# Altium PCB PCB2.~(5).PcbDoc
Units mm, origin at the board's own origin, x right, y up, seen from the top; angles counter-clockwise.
Board outline 101.6 x 109.09 mm, 2 copper layers (Top Layer, Bottom Layer); 25 components, 22 nets, 119 pads, 0 vias.
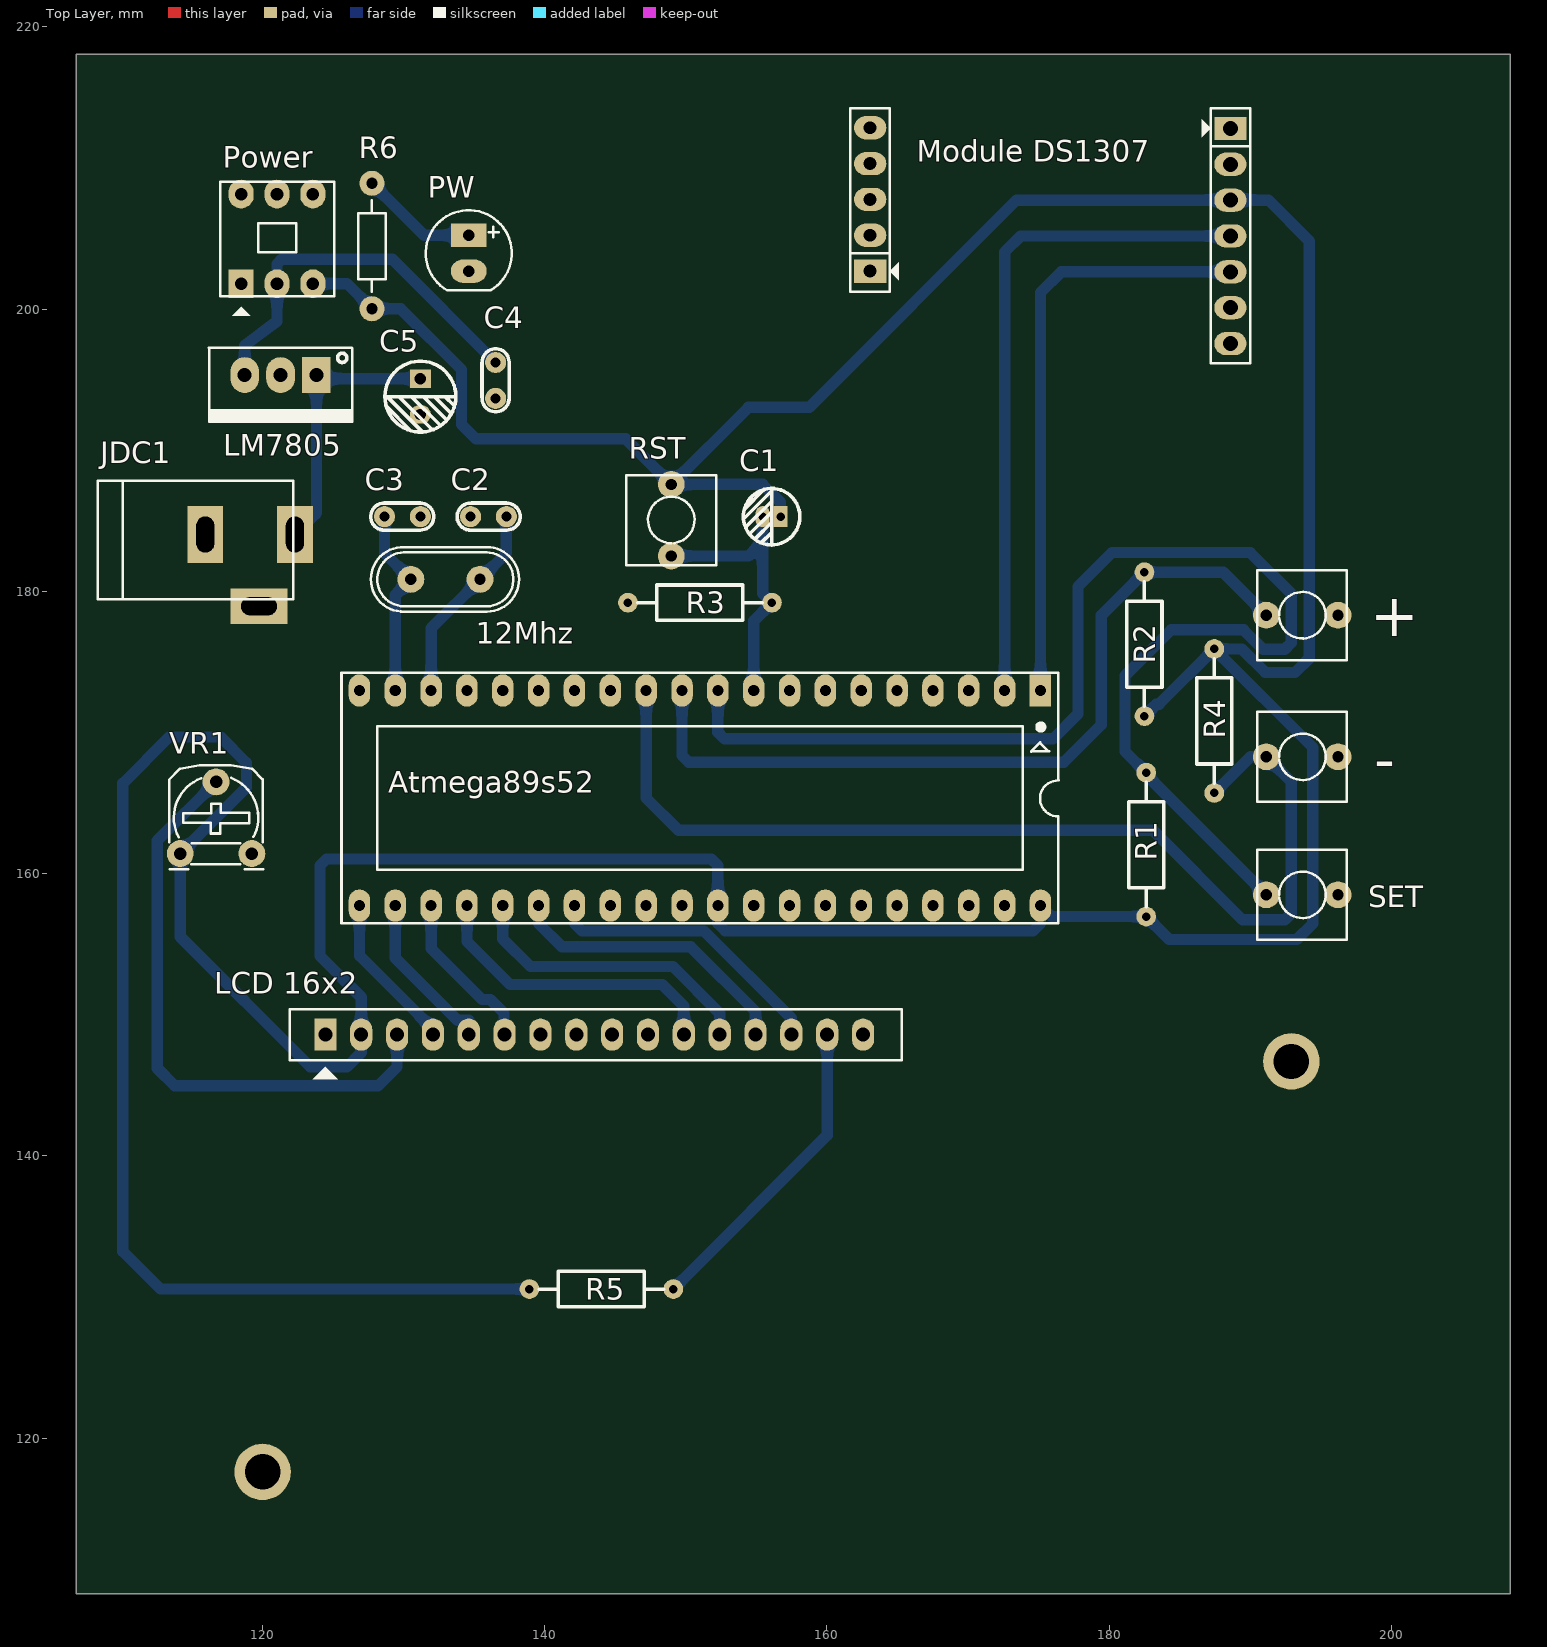
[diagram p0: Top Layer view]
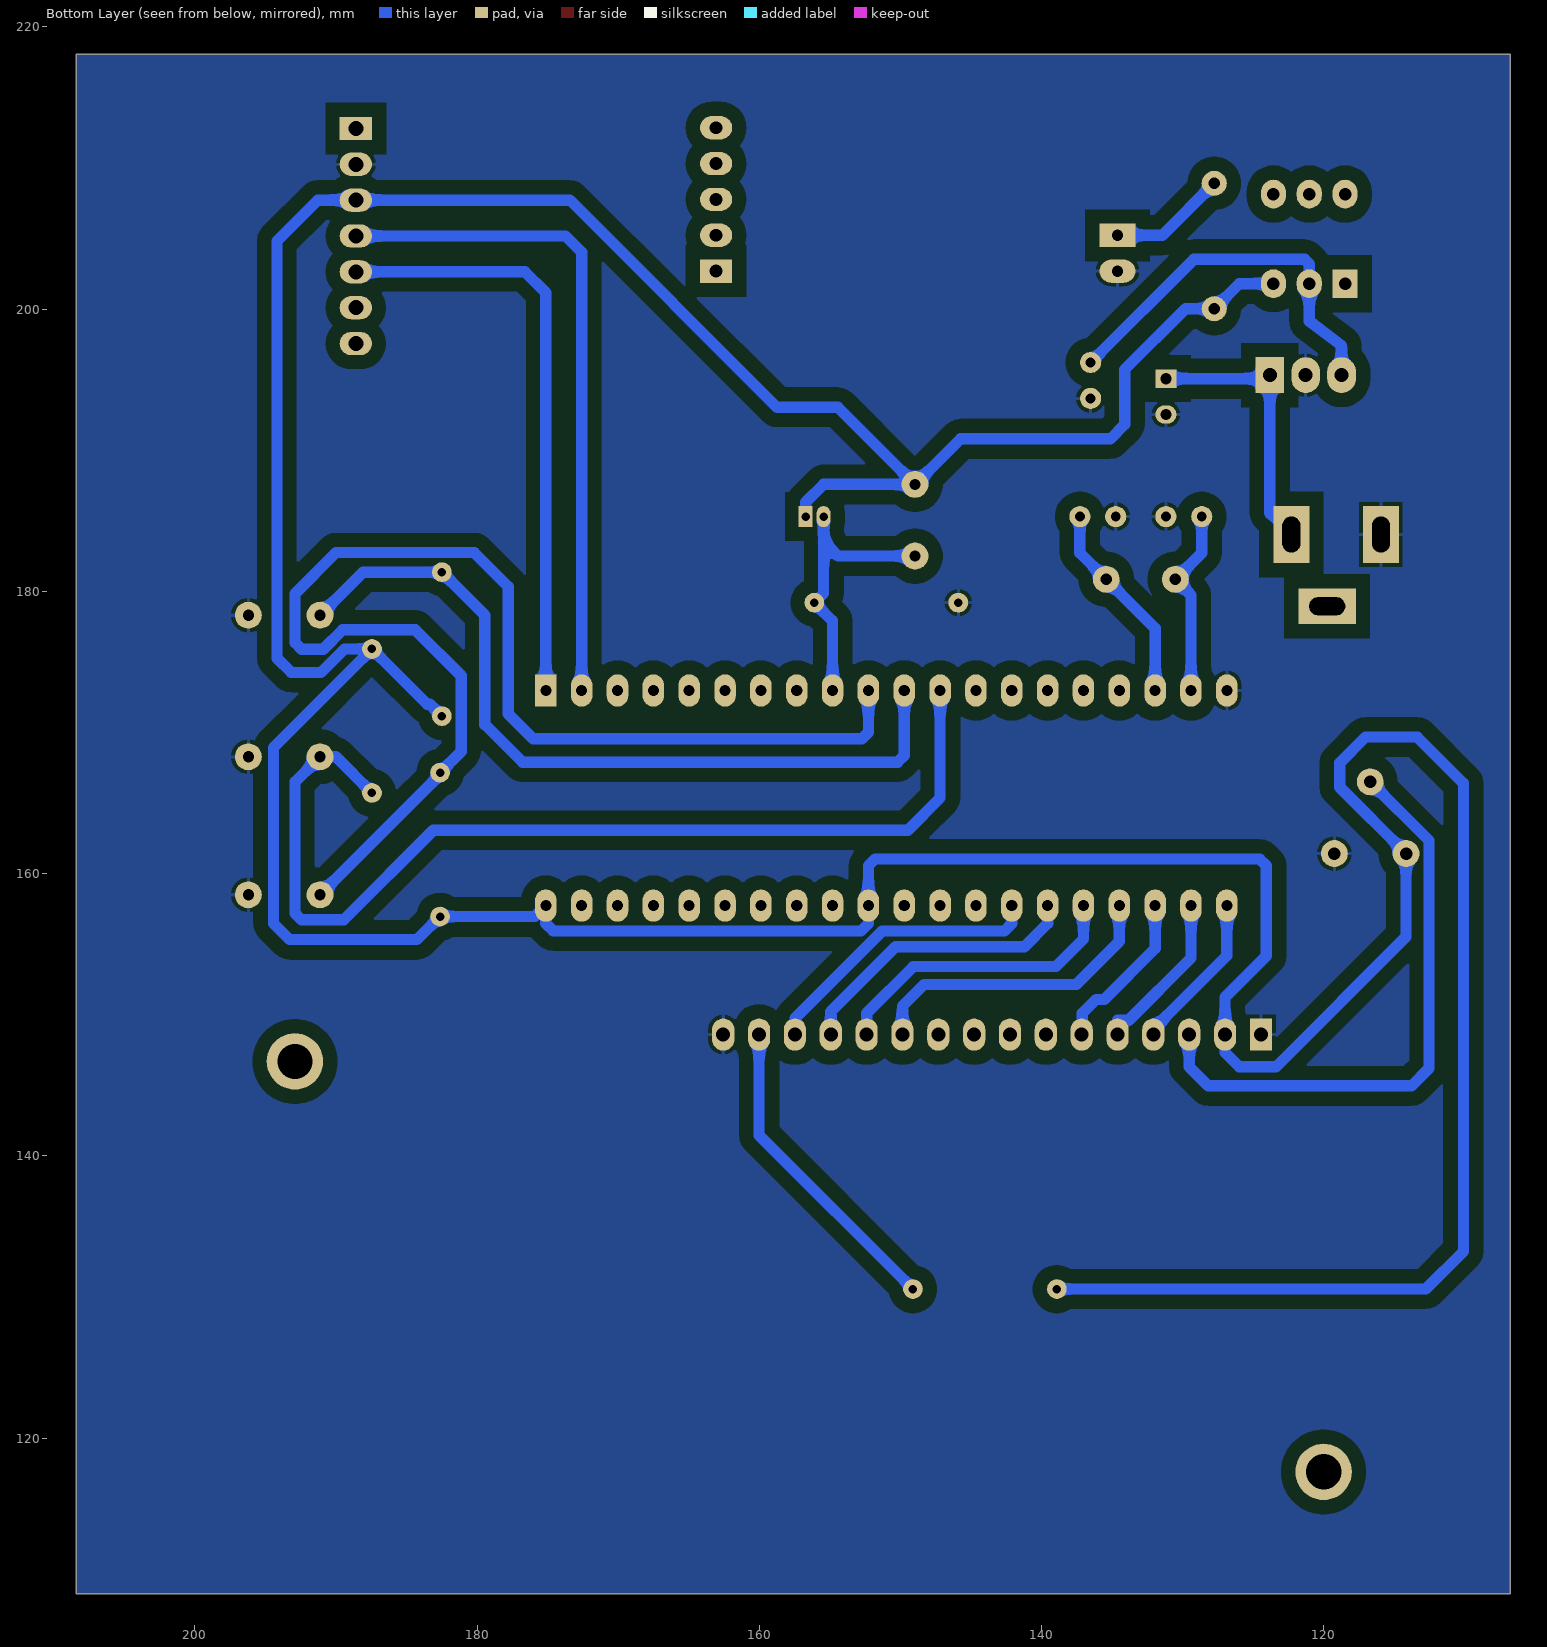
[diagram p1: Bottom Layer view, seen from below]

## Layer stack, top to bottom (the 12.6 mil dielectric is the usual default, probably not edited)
Top Solder: solder mask 0.0102, Solder Resist, Dk 3.5
Top Layer: signal copper 0.0356
Dielectric 1: dielectric 0.32, FR-4, Dk 4.8
Bottom Layer: signal copper 0.0356
Bottom Solder: solder mask 0.0102, Solder Resist, Dk 3.5

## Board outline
106.807,218.059 106.807,108.966 208.407,108.966 208.407,218.059

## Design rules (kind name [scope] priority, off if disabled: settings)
Clearance [All] p1: gap=0.2 ignorepadtopadclearanceinfootprint=FALSE
PolygonConnect [All] p1: connectstyle=Relief reliefconductorwidth=0.254 reliefentries=4 polygonreliefangle="90 Angle" airgapwidth=0.254
RoutingLayers [All] p1: top layer_v5=FALSE bottom layer_v5=TRUE
RoutingVias [All] p1: holewidth=0.711 width=1.27 viastyle="Through Hole" minholewidth=0.711 minwidth=1.27 maxholewidth=0.711 maxwidth=1.27
SolderMaskExpansion [All] p1: expansion=0.102 istentingtop=FALSE
Width [All] p1: maxlimit=0.8 minlimit=0.254 preferedwidth=0.8
29 further rules are at their usual default settings.

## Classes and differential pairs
component class Sheet2: C1 C2 C3 C4 C5 JDC1 R1 R2 R3 R4 R5 R6 VR1

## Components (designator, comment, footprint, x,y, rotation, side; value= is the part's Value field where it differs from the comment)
12Mhz "11Mhz" "Thach Anh 2 chan cam" 132.969,180.848 r0 top value=4Mhz (schematic designator Y1)
+ "SW" SW2 196.215,178.308 r180 top value="SW chip 2 pin" (schematic designator SW3)
- "SW" SW2 196.215,168.275 r180 top value="SW chip 2 pin" (schematic designator SW4)
Atmega89s52 "AT89S52" DIP40/W0.6 175.133,172.974 r180 top (schematic designator IC1)
C1 "10uF" "tu hoa 4mm" 156.083,185.293 r180 top
C2 "30pF" "tu gom" 136.017,185.293 r180 top
C3 "30pF" "tu gom" 129.921,185.293 r0 top
C4 "104" "tu gom" 136.525,194.945 r270 top
C5 "22uF" "tu hoa 5mm" 131.191,193.802 r270 top
JDC1 "Jack DC" DC-IN 119.126,181.483 r0 top value="Jac DC"
JP2 "JP5 PIN" JP5_1 163.068,202.692 r90 top value=JP5
"LCD 16x2" "LCD1602 XL" "LCD1602 with Jump" 124.46,148.59 r0 top (schematic designator LCD1)
LM7805 "LM7805" QTO-220 123.825,195.326 r180 top (schematic designator IC2)
"Module DS1307" "JP7 PIN" JP7_1 188.595,212.801 r270 top value=JP7 (schematic designator JP1)
Power "SW6A" SW6 118.491,201.803 r90 top value=SW6 (schematic designator SW5)
PW "LED" LED-5-RED 134.62,205.232 r270 top value="LED 3 ly Single Colour" (schematic designator LED1)
R1 "10K" "tro vach 1/4w" 182.626,162.052 r90 top
R2 "10K" "tro vach 1/4w" 182.499,176.256 r90 top
R3 "10k" "tro vach 1/4w" 151.003,179.197 r0 top
R4 "10K" "tro vach 1/4w" 187.452,170.815 r270 top
R5 "220R" "tro vach 1/4w" 144.018,130.556 r0 top
R6 "1k" R1/4W 127.762,208.915 r270 top value="R1/4W - 1K"
RST "SW" SW2 148.971,187.579 r270 top value="SW chip 2 pin" (schematic designator SW2)
SET "SW" SW2 196.215,158.496 r180 top value="SW chip 2 pin" (schematic designator SW1)
VR1 "1K" "Bien Tro Tam Giac Dung" 114.173,161.417 r0 top

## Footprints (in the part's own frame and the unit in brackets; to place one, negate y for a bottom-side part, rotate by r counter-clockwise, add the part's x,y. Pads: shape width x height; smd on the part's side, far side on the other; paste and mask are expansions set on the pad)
"Bien Tro Tam Giac Dung" [mil] "RM065"
  round 75 hole 35: 1(0,0) 2(100,200) 3(200,0)
  silkscreen extent -31,-44 231,246, body extent -28,-50 228,228, height 279
DC-IN [mil] "Jac DC input"
  rect 100x160 hole 50 slot 100 at 90 deg: 1(125,100) 2(-125,100)
  rect 160x100 hole 50 slot 100 at 0 deg: 3(25,-100)
  silkscreen extent -425,-80 120,250, body extent -410,-105 134,269, height 434
DIP40/W0.6 [mil] "40 PIN, W 600mil, Pin to pin 100mil"
  rect 60x90 hole 31: 1(0,0)
  oval 60x90 hole 31: 2(100,0) 3(200,0) 4(300,0) 5(400,0) 6(500,0) 7(600,0) 8(700,0) 9(800,0) 10(900,0) 11(1000,0) 12(1100,0) 13(1200,0) 14(1300,0) 15(1400,0) 16(1500,0) 17(1600,0) 18(1700,0) 19(1800,0) 20(1900,0) 21(1900,600) 22(1800,600) 23(1700,600) 24(1600,600) 25(1500,600) 26(1400,600) 27(1300,600) 28(1200,600) 29(1100,600) 30(1000,600) 31(900,600) 32(800,600) 33(700,600) 34(600,600) 35(500,600) 36(400,600) 37(300,600) 38(200,600) 39(100,600) 40(0,600)
  silkscreen extent -50,-50 1950,650, body extent -82,-10 1982,600, height 224
JP5_1 [mil] "JP5"
  rect 65x90 hole 36: 1(0,0)
  oval 65x90 hole 36: 2(100,0) 3(200,0) 4(300,0) 5(400,0)
  silkscreen extent -57,-80 455,55, body extent -55,-48 455,50, height 366
JP7_1 [mil] "JP7"
  rect 65x90 hole 42: 1(0,0)
  oval 65x90 hole 42: 2(100,0) 3(200,0) 4(300,0) 5(400,0) 6(500,0) 7(600,0)
  silkscreen extent -57,-80 655,55, body extent -53,-47 657,51, height 366
"LCD1602 with Jump" [mil] "LCD dipslay 16x2, 16 pin"
  rect 62x90 hole 39: 1(0,0)
  oval 62x90 hole 39: 2(100,0) 3(200,0) 4(300,0) 5(400,0) 6(500,0) 7(600,0) 8(700,0) 9(800,0) 10(900,0) 11(1000,0) 12(1100,0) 13(1200,0) 14(1300,0) 15(1400,0) 16(1500,0)
  silkscreen extent -100,-125 1608,70, body extent -320,-1353 2850,84, height 764
LED-5-RED [mil] "LED 2 PIN, 5 ly , Only colour,pin to pin 100mil"
  rect 65x100 hole 32: 1(0,0)
  oval 65x100 hole 32: 2(100,0)
  silkscreen extent -70,-120 154,120, body extent -65,-119 149,118, height 339
QTO-220 [mil] "TO-220 - 1-2-3"
  rect 80x100 hole 39: 1(0,0)
  oval 80x100 hole 39: 2(100,0) 3(200,0)
  silkscreen extent -100,-76 300,130, body extent -119,-64 322,121, height 755
R1/4W [mil] "R 1/4W, 2 Pin, 350mil"
  round 70 hole 31: 1(0,0) 2(350,0)
  silkscreen extent 48,-38 302,38, body extent -40,-47 386,47, height 111
SW2 [mil] "SW button 2pin, 250x 250 mil"
  round 75 hole 31: 1(0,0) 2(200,0)
  silkscreen extent -25,-125 225,125
SW6 [mil] "SW DTDP - 6Pin 260x300x300 mil"
  rect 80x70 hole 35: 1(0,0)
  oval 80x70 hole 35: 2(0,-100) 3(0,-200) 4(250,-200) 5(250,-100) 6(250,0)
  silkscreen extent -90,-260 285,58, body extent -33,-259 281,55, height 532
"Thach Anh 2 chan cam" [mm]
  round 1.905 hole 0.8: 1(-2.45,0) 2(2.45,0)
  silkscreen extent -5.28,-2.29 5.21,2.29, body extent -5.68,-2.36 5.68,2.29, height 3.5
"tro vach 1/4w" [mm]
  round 1.4 hole 0.6: 1(-5.1,0) 2(5.1,0)
  silkscreen extent -4.39,-1.25 4.42,1.25, body extent -5.38,-1.2 5.38,1.2, height 2.41
"tu gom" [mm] "Tu gom mini"
  round 1.5 hole 0.7: 1(-1.27,0) 2(1.27,0)
  silkscreen extent -2.25,-0.97 2.22,0.97, body extent -2.92,-0.85 2.92,0.85, height 6.12
"tu hoa 4mm" [mm]
  rect 1x1.5 hole 0.6: 1(-0.635,0)
  oval 1x1.5 hole 0.6: 2(0.635,0)
  silkscreen extent -2,-2 2.01,2.01, body extent -2.47,-2.47 2.58,2.58, height 14.81
"tu hoa 5mm" [mm]
  rect 1.3x1.5 hole 0.8: 1(-1.27,0)
  oval 1.3x1.5 hole 0.8: 2(1.27,0)
  silkscreen extent -2.51,-2.51 2.51,2.51, body extent -3.12,-3.18 3.23,3.18, height 14.55

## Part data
12Mhz: library part "Thach Anh 2 chan Cam", "Crystal For all Crystal 2pin."
+ - RST SET: library part SW2, "Switch button 2 pin"
Atmega89s52: "AT89S52, 8k Byte Flash Memory , 40 Pin"
C1: library part "Tu Hoa 10uF 25V 4x7", "Cắm"
C2 C3: library part "Tu gom 30pF 50V", "Cắm"
C4: library part "Tu gom 104 50V", "Cắm"
C5: library part "Tu Hoa 22uF 50V 5x10", "Cắm"
JDC1: library part DCIN, "Jac DC input"
JP2: library part JP5
"LCD 16x2": "LCD 1602 Xanh Lá"
LM7805: library part LM78xx, "On ap +, from + 5 to + 24VDC"
"Module DS1307": library part JP7
Power: "SW-DTDP - 6 Pin"
PW: "LED Single colour Green and Red"
R1 R2 R4 R5: library part "Tro Vach 1/4W 5% 220R", "Cắm"
R3: library part "Tro Vach 1/4W 5% 10k", "Căm"
R6: library part R1/4W, "Resistor 1/4W"
VR1: library part "Bien tro tam giac 1K Dung", "Cắm"

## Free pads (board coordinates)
  round 4 hole 2.5: 8(120.015,117.602) 8(192.913,146.685)

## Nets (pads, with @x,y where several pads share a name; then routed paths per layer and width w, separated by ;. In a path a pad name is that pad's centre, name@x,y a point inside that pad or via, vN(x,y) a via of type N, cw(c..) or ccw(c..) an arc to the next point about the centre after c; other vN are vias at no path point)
D4: "LCD 16x2.11" Atmega89s52.24 | length 21.8
  Bottom Layer w0.8: Atmega89s52.24 134.493,155.194 137.541,152.146 148.336,152.146 149.86,150.622 149.86,148.59
D5: "LCD 16x2.12" Atmega89s52.25 | length 21.4
  Bottom Layer w0.8: Atmega89s52.25 137.033,155.372 138.989,153.416 149.085,153.416 152.4,150.101 152.4,148.59
D6: "LCD 16x2.13" Atmega89s52.26 | length 20.9
  Bottom Layer w0.8: Atmega89s52.26 139.573,156.464 141.224,154.813 150.343,154.813 154.94,150.216 154.94,148.59
D7: "LCD 16x2.14" Atmega89s52.27 | length 20.6
  Bottom Layer w0.8: Atmega89s52.27 142.113,156.464 142.64,155.937 151.289,155.937 157.48,149.746 157.48,148.59
DOWN: -.2 Atmega89s52.12 R4.2 | length 73.7
  Bottom Layer w0.8: Atmega89s52.12 147.193,165.354 149.479,163.068 183.109,163.068 189.459,156.718 192.444,156.718 192.913,157.187 192.913,166.497 -.2 190.012,168.275 R4.2
EN: "LCD 16x2.6" Atmega89s52.23 | length 11.6
  Bottom Layer w0.8: Atmega89s52.23 131.953,154.686 135.56,151.079 136.144,151.079 137.113,150.11 137.113,148.637 137.16,148.59
GND: "LCD 16x2.1" "LCD 16x2.16" "Module DS1307.2" +.1 -.1 Atmega89s52.20 C2.2 C3.2 C4.2 C5.2 JDC1.2 LM7805.2 PW.2 R3.1 SET.1 VR1.3
NetC2_1: 12Mhz.2 Atmega89s52.18 C2.1 | length 14.5
  Bottom Layer w0.8: Atmega89s52.18 131.953,177.382 12Mhz.2 137.287,182.716 C2.1
NetC3_1: 12Mhz.1 Atmega89s52.19 C3.1 | length 13.6
  Bottom Layer w0.8: C3.1 128.651,182.716 12Mhz.1 129.413,179.742 Atmega89s52.19
NetC4_1: C4.1 LM7805.3 Power.2 | length 27.7
  Bottom Layer w0.8: LM7805.3 118.745,197.409 121.031,199.136 Power.2 121.031,203.2 121.361,203.53 129.21,203.53 C4.1
NetC5_1: C5.1 JDC1.1 LM7805.1 | length 19.3
  Bottom Layer w0.8: JDC1.1 123.825,185.547 LM7805.1@123.825,195.072 ; LM7805.1 LM7805.1@123.825,195.072 ; C5.1 LM7805.1@123.825,195.072
NetLCD1_15: "LCD 16x2.15" R5.2 | length 22.5
  Bottom Layer w0.8: R5.2 160.02,141.458 160.02,148.59
NetLED1_1: PW.1 R6.1 | length 8.4
  Bottom Layer w0.8: R6.1 131.445,205.232 PW.1
RS: "LCD 16x2.4" Atmega89s52.21 | length 11.3
  Bottom Layer w0.8: Atmega89s52.21 126.873,154.184 132.08,148.977 132.08,148.59
RST: Atmega89s52.9 C1.2 R3.2 RST.2 | length 20
  Bottom Layer w0.8: RST.2 154.432,182.499 155.448,183.515 ; Atmega89s52.9 154.813,177.907 R3.2 155.448,179.852 155.448,183.515 ; C1.2 155.448,183.515
RW: "LCD 16x2.5" Atmega89s52.22 | length 11.8
  Bottom Layer w0.8: Atmega89s52.22 129.413,154.013 133.82,149.606 134.62,149.606 134.62,148.59
SCL: "Module DS1307.5" Atmega89s52.1 | length 42.3
  Bottom Layer w0.8: Atmega89s52.1 175.133,201.168 176.606,202.641 188.595,202.641
SDA: "Module DS1307.4" Atmega89s52.2 | length 47.5
  Bottom Layer w0.8: Atmega89s52.2 172.593,204.038 173.736,205.181 188.595,205.181
SET: Atmega89s52.10 R1.2 SET.2 | length 92.8
  Bottom Layer w0.8: Atmega89s52.10 152.273,170.014 152.742,169.545 176.022,169.545 177.8,171.323 177.8,180.34 180.213,182.753 189.992,182.753 192.913,179.832 192.913,176.364 192.444,175.895 190.909,175.895 189.535,177.269 184.381,177.269 181.127,174.015 181.127,168.651 R1.2 182.626,167.005 SET.2
UP: +.2 Atmega89s52.11 R2.2 | length 57.6
  Bottom Layer w0.8: Atmega89s52.11 149.733,168.363 150.202,167.894 176.79,167.894 179.451,170.555 179.451,178.308 R2.2 188.087,181.356 +.2
VCC: "LCD 16x2.2" "Module DS1307.3" Atmega89s52.31 Atmega89s52.40 C1.1 Power.3 R1.1 R2.1 R4.1 R5.1 R6.2 RST.1 VR1.1 | length 362.1
  Bottom Layer w0.8: Power.3 125.984,201.803 R6.2 129.794,200.025 134.112,195.707 134.112,191.821 135.128,190.805 145.745,190.805 RST.1 ; R5.1 112.776,130.556 110.109,133.223 110.109,166.395 113.386,169.672 117.043,169.672 118.872,167.843 118.872,166.116 VR1.1 114.173,155.524 123.393,146.304 125.984,146.304 127,147.32 127,148.59 127,151.232 124.079,154.153 124.079,160.567 124.548,161.036 151.804,161.036 152.273,160.567 152.273,156.464 152.806,155.931 174.6,155.931 175.133,156.464 Atmega89s52.40 175.915,156.952 R1.1 184.257,155.321 193.294,155.321 194.437,156.464 194.437,168.93 R4.1 ; C1.1 156.718,186.309 155.448,187.579 RST.1 ; R2.1 183.349,172.006 183.543,172.006 R4.1 ; RST.1 154.432,193.04 158.75,193.04 173.431,207.721 188.595,207.721 191.287,207.721 194.183,204.826 194.183,175.26 193.167,174.244 191.069,174.244 189.398,175.915 R4.1
VEE: "LCD 16x2.3" VR1.2 | length 42.4
  Bottom Layer w0.8: VR1.2 112.547,162.331 112.547,146.202 113.792,144.958 128.194,144.958 129.54,146.304 129.54,148.59
pads on no net: "LCD 16x2.7" "LCD 16x2.8" "LCD 16x2.9" "LCD 16x2.10" "Module DS1307.1" "Module DS1307.6" "Module DS1307.7" Atmega89s52.3 Atmega89s52.4 Atmega89s52.5 Atmega89s52.6 Atmega89s52.7 Atmega89s52.8 Atmega89s52.13 Atmega89s52.14 Atmega89s52.15 Atmega89s52.16 Atmega89s52.17 Atmega89s52.28 Atmega89s52.29 Atmega89s52.30 Atmega89s52.32 Atmega89s52.33 Atmega89s52.34 Atmega89s52.35 Atmega89s52.36 Atmega89s52.37 Atmega89s52.38 Atmega89s52.39 JDC1.3 JP2.1 JP2.2 JP2.3 JP2.4 JP2.5 Power.1 Power.4 Power.5 Power.6

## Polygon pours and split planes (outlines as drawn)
GND on Bottom Layer "GND_L02_P000" (solid, pour order 0): 106.807,108.966 208.407,108.966 208.407,218.059 106.807,218.059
